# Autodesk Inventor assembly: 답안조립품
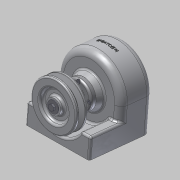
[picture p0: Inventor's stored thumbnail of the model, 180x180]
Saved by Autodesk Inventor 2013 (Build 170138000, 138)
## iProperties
Created: 2015-02
Part Number: 답안조립품
Document SubType Name: Assembly
Designer: Administrator
Author: Administrator
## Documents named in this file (14)
- C:\Users\Administrator\Desktop\450216V1022\답안조립품.iam
- C:\Users\Administrator\Desktop\450216V1022\본체.ipt
- C:\Users\Administrator\Desktop\450216V1022\베어링 6001.ipt
- C:\Users\Administrator\Desktop\450216V1022\축.ipt
- C:\Users\Administrator\Desktop\450216V1022\키5x5.ipt
- C:\Users\Administrator\Desktop\450216V1022\스퍼기어.ipt
- C:\Users\Administrator\Desktop\450216V1022\오일실.ipt
- C:\Users\Administrator\Desktop\450216V1022\축커버.ipt
- C:\Users\Administrator\Desktop\450216V1022\M3x0.5.ipt
- C:\Users\Administrator\Desktop\450216V1022\키4x4.ipt
- C:\Users\Administrator\Desktop\450216V1022\V-벨트풀리.ipt
- C:\Users\Administrator\Desktop\450216V1022\와샤.ipt
- C:\Users\Administrator\Desktop\450216V1022\M5x0.8.ipt
- M5x0.8.ipt
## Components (6 placed, 3 different names)
1. V-벨트풀리:1 — 플러쉬:1
2. M5x0.8:1 — 각도:2
3. M3x0.5:1 — 각도:1
4. M3x0.5:2
5. M3x0.5:3
6. M3x0.5:4
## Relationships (3: Angle 2, Flush 1)
- 각도:1 [Angle]: M3x0.5:1
- 플러쉬:1 [Flush]: V-벨트풀리:1
- 각도:2 [Angle]: M5x0.8:1
